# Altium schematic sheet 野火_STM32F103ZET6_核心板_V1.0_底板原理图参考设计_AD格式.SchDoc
size 297 x 209 mm
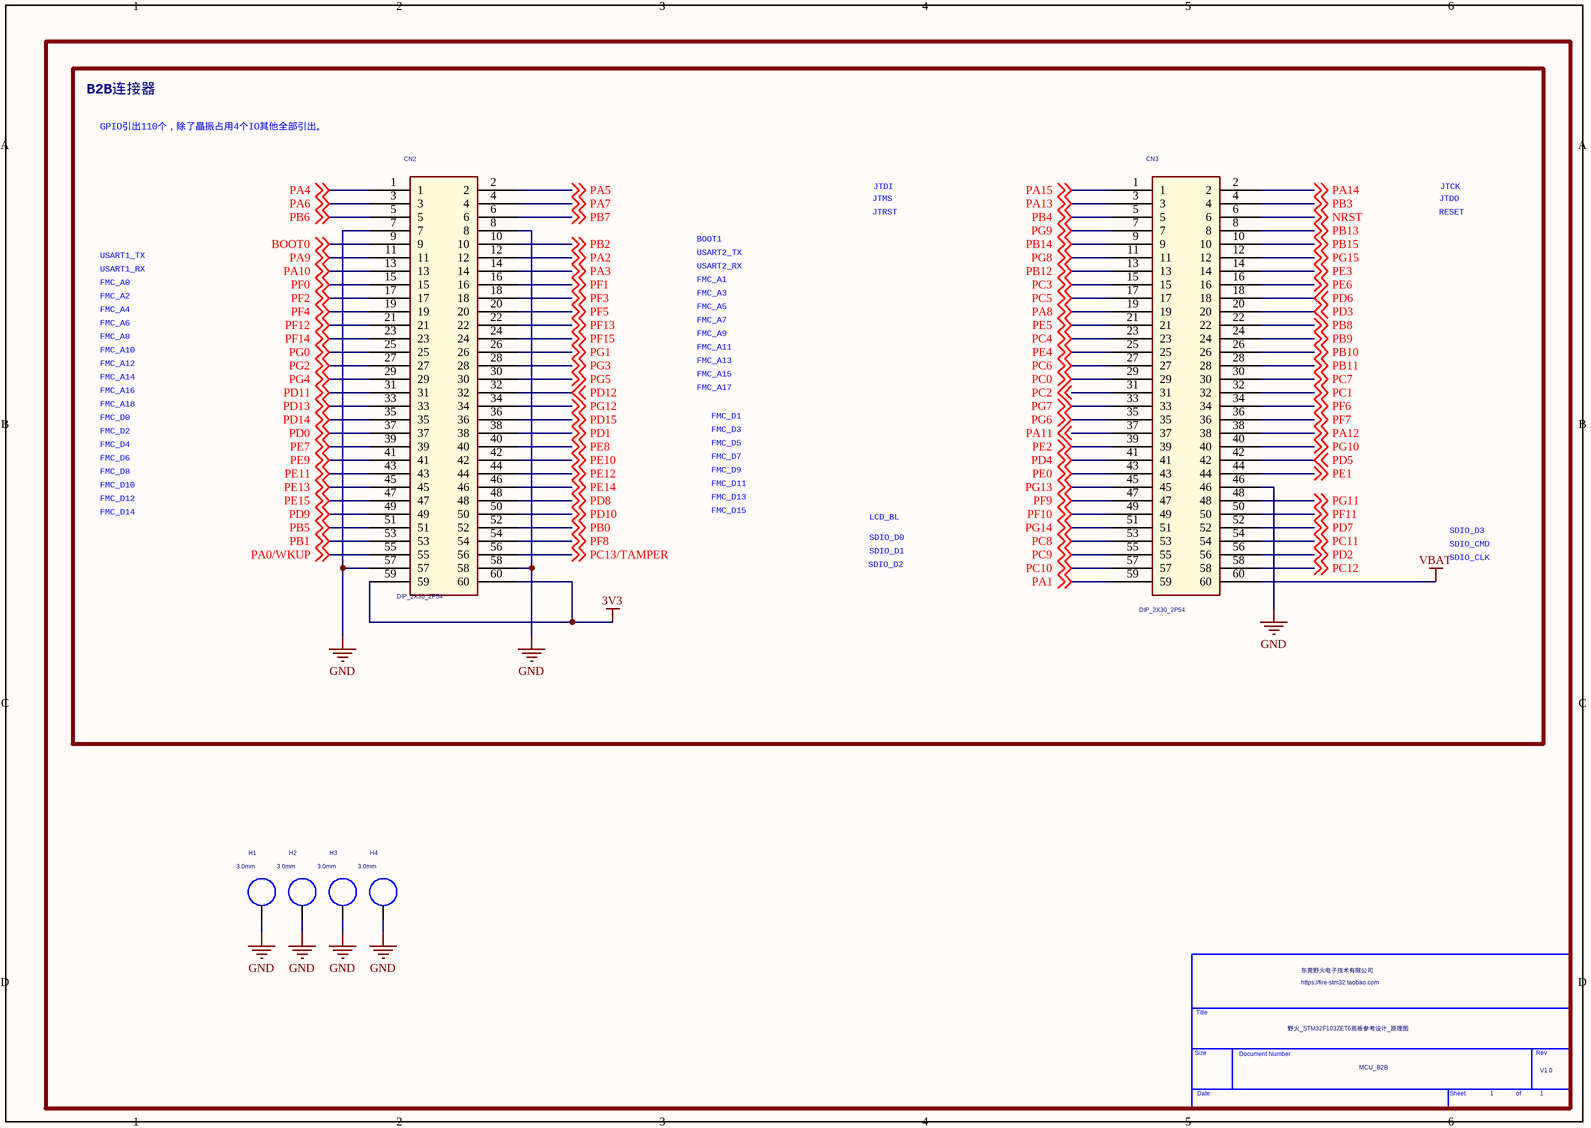
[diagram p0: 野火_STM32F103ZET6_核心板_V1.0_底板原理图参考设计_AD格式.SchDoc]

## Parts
*  Page Count: 1  OrgName: 东莞野火电子技术有限公司  Title: 野火_STM32F103ZET6底板参考设计_原理图  RevCode: V1.0  Doc: MCU_B2B  (hidden comment: TitleBlock_YHSCH)  (graphical)
CN2  DIP_2X30_2P54  [DIP-2X302P54]
CN3  DIP_2X30_2P54  [DIP-2X302P54]
H1  3.0mm  [t3-5p5]
H2  3.0mm  [t3-5p5]
H3  3.0mm  [t3-5p5]
H4  3.0mm  [t3-5p5]

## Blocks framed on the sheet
B2B连接器: CN2 CN3

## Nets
3V3: CN2.59 CN2.60
GND: CN2.7 CN2.8 CN2.57 CN2.58 CN3.46 H1.1(NC_1) H2.1(NC_1) H3.1(NC_1) H4.1(NC_1)
VBAT: CN3.60
BOOT0: CN2.9 ; off-sheet BOOT0
NRST: CN3.6 ; off-sheet NRST
PA0/WKUP: CN2.55 ; off-sheet PA0/WKUP
PA1: CN3.59 ; off-sheet PA1
PA2: CN2.12 ; off-sheet PA2
PA3: CN2.14 ; off-sheet PA3
PA4: CN2.1 ; off-sheet PA4
PA5: CN2.2 ; off-sheet PA5
PA6: CN2.3 ; off-sheet PA6
PA7: CN2.4 ; off-sheet PA7
PA8: CN3.19 ; off-sheet PA8
PA9: CN2.11 ; off-sheet PA9
PA10: CN2.13 ; off-sheet PA10
PA11: CN3.37 ; off-sheet PA11
PA12: CN3.38 ; off-sheet PA12
PA13: CN3.3 ; off-sheet PA13
PA14: CN3.2 ; off-sheet PA14
PA15: CN3.1 ; off-sheet PA15
PB0: CN2.52 ; off-sheet PB0
PB1: CN2.53 ; off-sheet PB1
PB2: CN2.10 ; off-sheet PB2
PB3: CN3.4 ; off-sheet PB3
PB4: CN3.5 ; off-sheet PB4
PB5: CN2.51 ; off-sheet PB5
PB6: CN2.5 ; off-sheet PB6
PB7: CN2.6 ; off-sheet PB7
PB8: CN3.22 ; off-sheet PB8
PB9: CN3.24 ; off-sheet PB9
PB10: CN3.26 ; off-sheet PB10
PB11: CN3.28 ; off-sheet PB11
PB12: CN3.13 ; off-sheet PB12
PB13: CN3.8 ; off-sheet PB13
PB14: CN3.9 ; off-sheet PB14
PB15: CN3.10 ; off-sheet PB15
PC0: CN3.29 ; off-sheet PC0
PC1: CN3.32 ; off-sheet PC1
PC2: CN3.31 ; off-sheet PC2
PC3: CN3.15 ; off-sheet PC3
PC4: CN3.23 ; off-sheet PC4
PC5: CN3.17 ; off-sheet PC5
PC6: CN3.27 ; off-sheet PC6
PC7: CN3.30 ; off-sheet PC7
PC8: CN3.53 ; off-sheet PC8
PC9: CN3.55 ; off-sheet PC9
PC10: CN3.57 ; off-sheet PC10
PC11: CN3.54 ; off-sheet PC11
PC12: CN3.58 ; off-sheet PC12
PC13/TAMPER: CN2.56 ; off-sheet PC13/TAMPER
PD0: CN2.37 ; off-sheet PD0
PD1: CN2.38 ; off-sheet PD1
PD2: CN3.56 ; off-sheet PD2
PD3: CN3.20 ; off-sheet PD3
PD4: CN3.41 ; off-sheet PD4
PD5: CN3.42 ; off-sheet PD5
PD6: CN3.18 ; off-sheet PD6
PD7: CN3.52 ; off-sheet PD7
PD8: CN2.48 ; off-sheet PD8
PD9: CN2.49 ; off-sheet PD9
PD10: CN2.50 ; off-sheet PD10
PD11: CN2.31 ; off-sheet PD11
PD12: CN2.32 ; off-sheet PD12
PD13: CN2.33 ; off-sheet PD13
PD14: CN2.35 ; off-sheet PD14
PD15: CN2.36 ; off-sheet PD15
PE0: CN3.43 ; off-sheet PE0
PE1: CN3.44 ; off-sheet PE1
PE2: CN3.39 ; off-sheet PE2
PE3: CN3.14 ; off-sheet PE3
PE4: CN3.25 ; off-sheet PE4
PE5: CN3.21 ; off-sheet PE5
PE6: CN3.16 ; off-sheet PE6
PE7: CN2.39 ; off-sheet PE7
PE8: CN2.40 ; off-sheet PE8
PE9: CN2.41 ; off-sheet PE9
PE10: CN2.42 ; off-sheet PE10
PE11: CN2.43 ; off-sheet PE11
PE12: CN2.44 ; off-sheet PE12
PE13: CN2.45 ; off-sheet PE13
PE14: CN2.46 ; off-sheet PE14
PE15: CN2.47 ; off-sheet PE15
PF0: CN2.15 ; off-sheet PF0
PF1: CN2.16 ; off-sheet PF1
PF2: CN2.17 ; off-sheet PF2
PF3: CN2.18 ; off-sheet PF3
PF4: CN2.19 ; off-sheet PF4
PF5: CN2.20 ; off-sheet PF5
PF6: CN3.34 ; off-sheet PF6
PF7: CN3.36 ; off-sheet PF7
PF8: CN2.54 ; off-sheet PF8
PF9: CN3.47 ; off-sheet PF9
PF10: CN3.49 ; off-sheet PF10
PF11: CN3.50 ; off-sheet PF11
PF12: CN2.21 ; off-sheet PF12
PF13: CN2.22 ; off-sheet PF13
PF14: CN2.23 ; off-sheet PF14
PF15: CN2.24 ; off-sheet PF15
PG0: CN2.25 ; off-sheet PG0
PG1: CN2.26 ; off-sheet PG1
PG2: CN2.27 ; off-sheet PG2
PG3: CN2.28 ; off-sheet PG3
PG4: CN2.29 ; off-sheet PG4
PG5: CN2.30 ; off-sheet PG5
PG6: CN3.35 ; off-sheet PG6
PG7: CN3.33 ; off-sheet PG7
PG8: CN3.11 ; off-sheet PG8
PG9: CN3.7 ; off-sheet PG9
PG10: CN3.40 ; off-sheet PG10
PG11: CN3.48 ; off-sheet PG11
PG12: CN2.34 ; off-sheet PG12
PG13: CN3.45 ; off-sheet PG13
PG14: CN3.51 ; off-sheet PG14
PG15: CN3.12 ; off-sheet PG15

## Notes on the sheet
- GPIO引出110个，除了晶振占用4个IO其他全部引出。
- JTMS
- JTDI
- JTDO
- JTCK
- USART1_RX
- USART1_TX
- USART2_RX
- USART2_TX
- BOOT1
- JTRST
- RESET
- FMC_A0
- FMC_A2
- FMC_A4
- FMC_A6
- FMC_A8
- FMC_A1
- FMC_A3
- FMC_A5
- FMC_A7
- FMC_A9
- FMC_A10
- FMC_A12
- FMC_A14
- FMC_A16
- FMC_A18
- FMC_A11
- FMC_A13
- FMC_A15
- FMC_A17
- FMC_D0
- FMC_D2
- FMC_D4
- FMC_D6
- FMC_D8
- FMC_D1
- FMC_D3
- FMC_D5
- FMC_D7
- FMC_D9
- FMC_D10
- FMC_D12
- FMC_D14
- FMC_D11
- FMC_D13
- FMC_D15
- SDIO_D0
- LCD_BL
- SDIO_D3
- SDIO_D2
- SDIO_D1
- SDIO_CLK
- SDIO_CMD

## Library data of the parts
CN2 CN3 = DIP_2X40_0
H1 H2 = SPACER_0: FASTENER, STANDOFF 4.5MMX3.53XM3.0X0.5 ROUND THR .635"L BRASS; CLASS: IC; CAD_APPROVED: Yes; ASSY_OPT: DNP; MFG_PN01: MSS251-R-1-A-16; MFG_NAME01: UNICORP; AGILE_PN: 280-76498
H3 H4 = SPACER_0: FASTENER, STANDOFF 4.5MMX3.53XM3.0X0.5 ROUND THR .635"L BRASS; CLASS: IC; AGILE_PN: 280-76498; MFG_NAME01: UNICORP; MFG_PN01: MSS251-R-1-A-16; ASSY_OPT: DNP; CAD_APPROVED: Yes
